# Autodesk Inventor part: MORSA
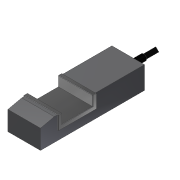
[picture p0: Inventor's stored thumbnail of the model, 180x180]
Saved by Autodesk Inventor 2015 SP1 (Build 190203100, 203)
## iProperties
Created: 2014-10
Part Number: MORSA
Material: Generic
Document SubType Name: Modeling
Designer: Guilherme Augusto
Density: 1 g/cm^3
Appearance: Default
Author: Guilherme Augusto
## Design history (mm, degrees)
sketch "Sketch1"
  geometry: L1 (-50, 32)-(-50, 0); L2 (-50, 0)-(50, 0); L3 (50, 0)-(50, 32); L4 (50, 32)-(62, 32); L5 (62, 32)-(62, -12); L6 (62, -12)-(-62, -12); L7 (-62, -12)-(-62, 32); L8 (-62, 32)-(-50, 32); 2 further points
  constraints: 16 end point, 6 perpendicular, 1 coincident, 1 collinear, 1 horizontal, 1 midpoint, 1 point on line, 1 vertical
  dimensions: "d0" = 12 distance of L1.start L7.end; "d1" = 32 distance of L1.start L1.end; "d2" = 12 distance between parallel lines of L2 L6 (= d0); "d3" = 100 distance between parallel lines of L1 L3
extrude "Extrusion1" new body sketch "Sketch1" stored distance "d4" = 113; taper "d5" = 0 deg
sketch "Sketch2"
  geometry: L1 (-62, -12)-(-62, 32) reference; L2 (62, 32)-(62, -12) reference; L3 (62, -12)-(-62, -12) reference; L4 (-62, 31)-(-72, 31); L5 (-72, 31)-(-117, 21); L6 (-117, 21)-(-117, -42); L7 (-117, -42)-(222, -42); L8 (222, -42)-(222, 31); L9 (222, 31)-(62, 31); L10 (62, -12)-(62, 31); L11 (-62, 31)-(-62, -12); 1 further point
  constraints: 16 end point, 4 perpendicular, 3 point on line, 2 collinear, 1 horizontal
  dimensions: "d9" = 160 distance of L8.end L9.end; "d10" = 55 distance between parallel lines of L6 L1; "d11" = 10 distance of L4.start L4.end; "d12" = 30 distance between parallel lines of L3 L7; "d13" = 10 vertical distance of L4.end L5.end; "d14" = 1 distance from line of L1.end L4
extrude "Extrusion2" join sketch "Sketch2" stored distance "d15" = 106; taper "d16" = 0 deg
sketch "Sketch3"
  geometry: C1 r 10 at (53, 42); 1 further point
  constraints: 1 centre point, 1 coincident
  dimensions: "d17" = 20 diameter of C1
extrude "Extrusion3" join sketch "Sketch3" distance "d18" = 50; taper "d19" = 0 deg
sketch "Sketch4"
  geometry: L1 (0, 10)-(10, 0); L2 (10, 0)-(0, -10); L3 (0, -10)-(-10, 0); L4 (-10, 0)-(0, 10); 2 further points
  constraints: 8 end point, 1 coincident, 1 vertical alignment, 9 other
  dimensions: "d21" = 20 distance of L2.end L1.start
extrude "Extrusion4" join sketch "Sketch4" distance "d22" = 40; taper "d23" = 0 deg
chamfer "Chamfer1" distance "d6" = 1; stored, may be unused: second distance "d7" = 2, angle "d8" = 45 deg
body "Solid1"
